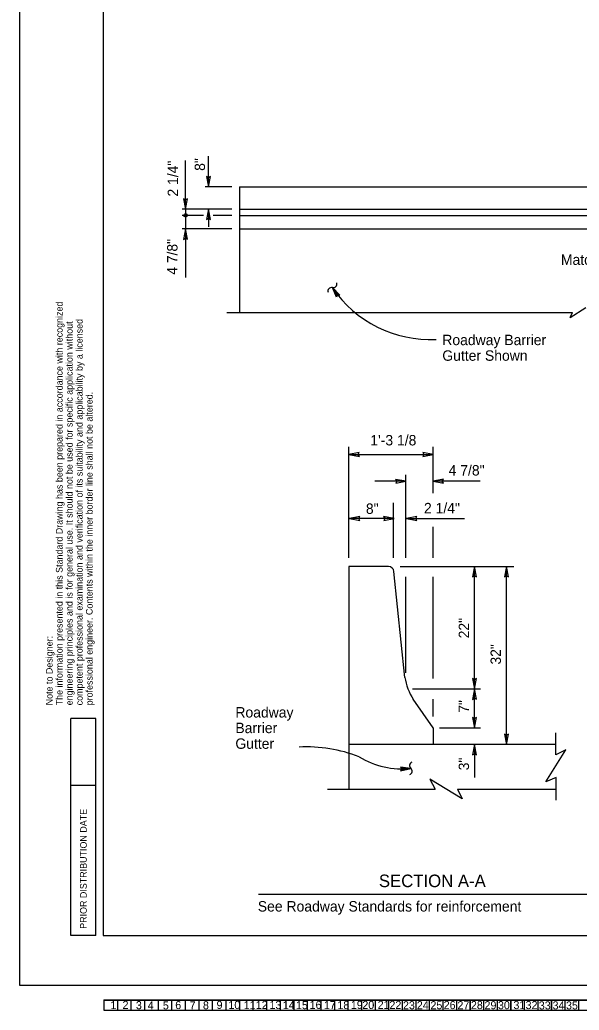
# Model space of a CAD drawing. Extents: x 0 to 2.83, y -0.03 to 1.83.
# Drawn here: x 0 to 0.699, y -0.031 to 1.206 of the extents above; entities that cross this region are included whole.
import ezdxf

# ---------------------------------------------------------------- set-up
doc = ezdxf.new("R2010")
doc.units = 0
for name, color, linetype in [('1', 7, 'Continuous'), ('10', 7, 'Continuous'), ('11', 7, 'Continuous'), ('12', 7, 'Continuous'), ('13', 7, 'Continuous'), ('14', 7, 'Continuous'), ('15', 7, 'Continuous'), ('16', 7, 'Continuous'), ('17', 7, 'Continuous'), ('18', 7, 'Continuous'), ('19', 7, 'Continuous'), ('2', 7, 'Continuous'), ('20', 7, 'Continuous'), ('21', 7, 'Continuous'), ('22', 7, 'Continuous'), ('23', 7, 'Continuous'), ('24', 7, 'Continuous'), ('25', 7, 'Continuous'), ('26', 7, 'Continuous'), ('27', 7, 'Continuous'), ('28', 7, 'Continuous'), ('29', 7, 'Continuous'), ('3', 7, 'Continuous'), ('30', 7, 'Continuous'), ('31', 7, 'Continuous'), ('32', 7, 'Continuous'), ('33', 7, 'Continuous'), ('34', 7, 'Continuous'), ('35', 7, 'Continuous'), ('4', 7, 'Continuous'), ('40', 7, 'Continuous'), ('5', 7, 'Continuous'), ('50', 7, 'Continuous'), ('54', 7, 'Continuous'), ('55', 7, 'Continuous'), ('57', 7, 'Continuous'), ('6', 7, 'Continuous'), ('62', 7, 'Continuous'), ('63', 7, 'Continuous'), ('7', 7, 'Continuous'), ('8', 7, 'Continuous'), ('9', 7, 'Continuous')]:
    doc.layers.add(name, color=color, linetype=linetype)

msp = doc.modelspace()

# ---------------------------------------------------------------- linework, layer by layer
at = {"layer": '40'}
for p, q in [((0.2743, 0.9973), (0.8822, 0.9973)), ((0.2743, 0.9973), (0.2743, 0.8407)), ((0.2743, 0.9696), (0.8822, 0.9696)), ((0.2743, 0.9618), (0.8822, 0.9618)), ((0.2743, 0.9448), (0.8822, 0.9448))]:
    msp.add_line(p, q, dxfattribs=at)
at = {"layer": '50'}
for p, q in [((0.4603, 0.5232), (0.411, 0.5232)), ((0.411, 0.5232), (0.411, 0.301)), ((0.4808, 0.3848), (0.4672, 0.517)), ((0.5161, 0.3218), (0.4912, 0.3576)), ((0.5161, 0.3218), (0.5161, 0.301)), ((0.411, 0.301), (0.411, 0.2454)), ((0.6693, 0.301), (0.411, 0.301))]:
    msp.add_line(p, q, dxfattribs=at)
for centre, radius, start, end in [((0.4603, 0.5162), 0.00694, 5.8395, 90), ((0.5494, 0.3955), 0.0694, 188.8949, 213.1061)]:
    msp.add_arc(centre, radius, start, end, dxfattribs=at)
at = {"layer": '54'}
for points in [[(0.2356, 0.9973), (0.238, 1.0103), (0.2356, 1.0088), (0.2332, 1.0102)], [(0.207, 0.9696), (0.2094, 0.9826), (0.207, 0.981), (0.2046, 0.9824)], [(0.2356, 0.9696), (0.2333, 0.9566), (0.2356, 0.9581), (0.238, 0.9567)], [(0.207, 0.9448), (0.2046, 0.9318), (0.207, 0.9333), (0.2094, 0.932)], [(0.411, 0.6632), (0.424, 0.6608), (0.4225, 0.6632), (0.4239, 0.6656)], [(0.5161, 0.6632), (0.5031, 0.6656), (0.5046, 0.6632), (0.5032, 0.6608)], [(0.4822, 0.6298), (0.4692, 0.6321), (0.4707, 0.6298), (0.4694, 0.6274)], [(0.5161, 0.6298), (0.5291, 0.6274), (0.5276, 0.6298), (0.5289, 0.6322)], [(0.4117, 0.5833), (0.4247, 0.5809), (0.4232, 0.5833), (0.4246, 0.5857)], [(0.4673, 0.5833), (0.4543, 0.5857), (0.4558, 0.5833), (0.4544, 0.5809)], [(0.4829, 0.5833), (0.4959, 0.5809), (0.4944, 0.5833), (0.4957, 0.5857)], [(0.5677, 0.5232), (0.5653, 0.5102), (0.5677, 0.5117), (0.5701, 0.5104)], [(0.6077, 0.5232), (0.6053, 0.5102), (0.6077, 0.5117), (0.6101, 0.5104)], [(0.5677, 0.3704), (0.5701, 0.3834), (0.5677, 0.3819), (0.5653, 0.3833)], [(0.5677, 0.3704), (0.5653, 0.3574), (0.5677, 0.3589), (0.5701, 0.3576)], [(0.5677, 0.3218), (0.5701, 0.3348), (0.5677, 0.3333), (0.5653, 0.3346)], [(0.6077, 0.301), (0.6101, 0.314), (0.6077, 0.3125), (0.6053, 0.3138)], [(0.5677, 0.301), (0.5653, 0.288), (0.5677, 0.2895), (0.5701, 0.2881)]]:
    msp.add_lwpolyline(points, close=True, dxfattribs=at)
at = {"layer": '55'}
for p, q in [((0.207, 0.9696), (0.207, 1.0302)), ((0.2356, 0.9973), (0.2356, 1.0357)), ((0.2647, 0.9973), (0.2315, 0.9973)), ((0.2647, 0.9696), (0.2028, 0.9696)), ((0.207, 0.9696), (0.207, 0.9448)), ((0.2356, 0.9696), (0.2356, 0.9476)), ((0.2294, 0.9618), (0.2028, 0.9618)), ((0.2647, 0.9618), (0.2414, 0.9618)), ((0.2647, 0.9448), (0.2028, 0.9448)), ((0.207, 0.9448), (0.207, 0.8841)), ((0.6871, 0.8343), (0.707, 0.8466)), ((0.2587, 0.8405), (0.6796, 0.8405)), ((0.6743, 0.8404), (0.6902, 0.8404)), ((0.6871, 0.8343), (0.6902, 0.8404)), ((0.411, 0.5343), (0.411, 0.6728)), ((0.5161, 0.6147), (0.5161, 0.6728)), ((0.411, 0.6632), (0.5161, 0.6632)), ((0.4822, 0.5343), (0.4822, 0.6376)), ((0.4822, 0.6298), (0.4434, 0.6298)), ((0.5749, 0.6298), (0.5161, 0.6298)), ((0.4666, 0.5343), (0.4666, 0.6027)), ((0.4673, 0.5833), (0.4117, 0.5833)), ((0.4829, 0.5833), (0.5555, 0.5833)), ((0.5161, 0.5343), (0.5161, 0.573)), ((0.4749, 0.5232), (0.6171, 0.5232)), ((0.5677, 0.3704), (0.5677, 0.5232)), ((0.6077, 0.301), (0.6077, 0.5232)), ((0.4822, 0.3906), (0.4822, 0.5105)), ((0.5161, 0.3834), (0.5161, 0.5105)), ((0.4904, 0.3704), (0.5753, 0.3704)), ((0.5677, 0.3218), (0.5677, 0.3704)), ((0.5161, 0.3358), (0.5161, 0.3575)), ((0.5241, 0.3218), (0.5753, 0.3218)), ((0.6693, 0.288), (0.6693, 0.3156)), ((0.5677, 0.301), (0.5677, 0.2597)), ((0.657, 0.2542), (0.6818, 0.2942)), ((0.6818, 0.2942), (0.6693, 0.288)), ((0.6697, 0.2599), (0.657, 0.2542)), ((0.6697, 0.2315), (0.6697, 0.2599)), ((0.5522, 0.2331), (0.5122, 0.2579)), ((0.5122, 0.2579), (0.5185, 0.2454)), ((0.3842, 0.2454), (0.5185, 0.2454)), ((0.5467, 0.2454), (0.5522, 0.2331)), ((0.5467, 0.2454), (0.6697, 0.2454))]:
    msp.add_line(p, q, dxfattribs=at)
for points in [[(0.3903, 0.8716), (0.3995, 0.8622), (0.3973, 0.8621), (0.392, 0.8691), (0.3965, 0.8615), (0.3956, 0.8595), (0.3903, 0.8716)], [(0.3935, 0.8679), (0.3973, 0.8628), (0.3983, 0.8628), (0.3911, 0.8704), (0.3955, 0.8609), (0.3959, 0.8619), (0.3927, 0.8671)], [(0.4883, 0.2712), (0.4753, 0.2728), (0.4766, 0.271), (0.4853, 0.271), (0.4766, 0.27), (0.4756, 0.2681), (0.4883, 0.2712)], [(0.4835, 0.2715), (0.4771, 0.2714), (0.4765, 0.2723), (0.4869, 0.2711), (0.4767, 0.2688), (0.4772, 0.2698), (0.4833, 0.2703)]]:
    msp.add_lwpolyline(points, dxfattribs=at)
msp.add_circle((0.207, 0.9618), 0.00214, dxfattribs=at)
for centre, radius, start, end in [((0.3894, 0.867), 0.0047, 78.7125, 195.1185), ((0.3913, 0.8762), 0.0047, 258.7125, 15.1185), ((0.5124, 0.954), 0.1473, 214.0105, 272.8594), ((0.3581, 0.1167), 0.1813, 68.7429, 92.9324), ((0.4767, 0.37), 0.0995, 237.9072, 276.7321), ((0.4914, 0.2747), 0.0047, 112.0894, 228.4955), ((0.4852, 0.2677), 0.0047, 292.0894, 48.4955)]:
    msp.add_arc(centre, radius, start, end, dxfattribs=at)
at = {"layer": '57'}
msp.add_line((0.7833, 0.1135), (0.2981, 0.1135), dxfattribs=at)
at = {"layer": '62'}
for p, q in [((0.1049, -0.018), (1.1717, -0.018)), ((0.1049, -0.018), (0.1049, -0.0307)), ((0.105, -0.0181), (1.1718, -0.0181)), ((0.105, -0.0181), (0.105, -0.0308)), ((0.1219, -0.018), (0.1219, -0.0307)), ((0.1219, -0.0181), (0.1219, -0.0308)), ((0.1388, -0.018), (0.1388, -0.0307)), ((0.1388, -0.0181), (0.1388, -0.0308)), ((0.1557, -0.018), (0.1557, -0.0307)), ((0.1558, -0.0181), (0.1558, -0.0308)), ((0.1727, -0.018), (0.1727, -0.0307)), ((0.1727, -0.0181), (0.1727, -0.0308)), ((0.1896, -0.018), (0.1896, -0.0307)), ((0.1896, -0.0181), (0.1896, -0.0308)), ((0.2065, -0.018), (0.2065, -0.0307)), ((0.2066, -0.0181), (0.2066, -0.0308)), ((0.2235, -0.018), (0.2235, -0.0307)), ((0.2235, -0.0181), (0.2235, -0.0308)), ((0.2404, -0.018), (0.2404, -0.0307)), ((0.2404, -0.0181), (0.2404, -0.0308)), ((0.2573, -0.018), (0.2573, -0.0307)), ((0.2574, -0.0181), (0.2574, -0.0308)), ((0.2743, -0.018), (0.2743, -0.0307)), ((0.2743, -0.0181), (0.2743, -0.0308)), ((0.2912, -0.018), (0.2912, -0.0307)), ((0.2912, -0.0181), (0.2912, -0.0308)), ((0.3081, -0.018), (0.3081, -0.0307)), ((0.3082, -0.0181), (0.3082, -0.0308)), ((0.3251, -0.018), (0.3251, -0.0307)), ((0.3251, -0.0181), (0.3251, -0.0308)), ((0.342, -0.018), (0.342, -0.0307)), ((0.342, -0.0181), (0.342, -0.0308)), ((0.3589, -0.018), (0.3589, -0.0307)), ((0.359, -0.0181), (0.359, -0.0308)), ((0.3759, -0.018), (0.3759, -0.0307)), ((0.3759, -0.0181), (0.3759, -0.0308)), ((0.3928, -0.018), (0.3928, -0.0307)), ((0.3928, -0.0181), (0.3928, -0.0308)), ((0.4097, -0.018), (0.4097, -0.0307)), ((0.4098, -0.0181), (0.4098, -0.0308)), ((0.4267, -0.018), (0.4267, -0.0307)), ((0.4267, -0.0181), (0.4267, -0.0308)), ((0.4436, -0.018), (0.4436, -0.0307)), ((0.4436, -0.0181), (0.4436, -0.0308)), ((0.4605, -0.018), (0.4605, -0.0307)), ((0.4606, -0.0181), (0.4606, -0.0308)), ((0.4775, -0.018), (0.4775, -0.0307)), ((0.4775, -0.0181), (0.4775, -0.0308)), ((0.4944, -0.018), (0.4944, -0.0307)), ((0.4944, -0.0181), (0.4944, -0.0308)), ((0.5113, -0.018), (0.5113, -0.0307)), ((0.5114, -0.0181), (0.5114, -0.0308)), ((0.5283, -0.018), (0.5283, -0.0307)), ((0.5283, -0.0181), (0.5283, -0.0308)), ((0.5452, -0.018), (0.5452, -0.0307)), ((0.5452, -0.0181), (0.5452, -0.0308)), ((0.5621, -0.018), (0.5621, -0.0307)), ((0.5622, -0.0181), (0.5622, -0.0308)), ((0.5791, -0.018), (0.5791, -0.0307)), ((0.5791, -0.0181), (0.5791, -0.0308)), ((0.596, -0.018), (0.596, -0.0307)), ((0.596, -0.0181), (0.596, -0.0308)), ((0.6129, -0.018), (0.6129, -0.0307)), ((0.613, -0.0181), (0.613, -0.0308)), ((0.6299, -0.018), (0.6299, -0.0307)), ((0.6299, -0.0181), (0.6299, -0.0308)), ((0.6468, -0.018), (0.6468, -0.0307)), ((0.6468, -0.0181), (0.6468, -0.0308)), ((0.6637, -0.018), (0.6637, -0.0307)), ((0.6638, -0.0181), (0.6638, -0.0308)), ((0.6807, -0.018), (0.6807, -0.0307)), ((0.6807, -0.0181), (0.6807, -0.0308)), ((0.6976, -0.018), (0.6976, -0.0307)), ((0.6976, -0.0181), (0.6976, -0.0308)), ((0.1049, -0.0307), (1.1717, -0.0307)), ((0.105, -0.0308), (1.1718, -0.0308))]:
    msp.add_line(p, q, dxfattribs=at)
at = {"layer": '63'}
for p, q in [((0, 0), (0, 1.8333)), ((0.0638, 0.0624), (0.0638, 0.3333)), ((0.0951, 0.3333), (0.0638, 0.3333)), ((0.0951, 0.0624), (0.0951, 0.3333)), ((0.0951, 0.2499), (0.0638, 0.2499)), ((0.0951, 0.0624), (0.0638, 0.0624)), ((2.8333, 0), (0, 0))]:
    msp.add_line(p, q, dxfattribs=at)
msp.add_lwpolyline([(2.7292, 1.7708), (0.1042, 1.7708), (0.1042, 0.0624), (2.7292, 0.0624)], close=True, dxfattribs=at)

# ---------------------------------------------------------------- texts
at = {"layer": '1'}
for p in [(0.1132, -0.0294), (0.1132, -0.0295)]:
    msp.add_text('1', height=0.01, rotation=360, dxfattribs=at).set_placement(p)
at = {"layer": '10'}
msp.add_text('10', height=0.01, rotation=360, dxfattribs=at).set_placement((0.2605, -0.0293))
msp.add_text('10', height=0.01, rotation=360, dxfattribs=at).set_placement((0.2605, -0.0293))
at = {"layer": '11'}
msp.add_text('11', height=0.01, rotation=360, dxfattribs=at).set_placement((0.2796, -0.0294))
msp.add_text('11', height=0.01, rotation=360, dxfattribs=at).set_placement((0.2796, -0.0294))
at = {"layer": '12'}
msp.add_text('12', height=0.01, rotation=360, dxfattribs=at).set_placement((0.2947, -0.0293))
msp.add_text('12', height=0.01, rotation=360, dxfattribs=at).set_placement((0.2947, -0.0293))
at = {"layer": '13'}
msp.add_text('13', height=0.01, rotation=360, dxfattribs=at).set_placement((0.3118, -0.0293))
msp.add_text('13', height=0.01, rotation=360, dxfattribs=at).set_placement((0.3118, -0.0293))
at = {"layer": '14'}
for p in [(0.3284, -0.0294), (0.3285, -0.0294)]:
    msp.add_text('14', height=0.01, rotation=360, dxfattribs=at).set_placement(p)
at = {"layer": '15'}
msp.add_text('15', height=0.01, rotation=360, dxfattribs=at).set_placement((0.3449, -0.0295))
msp.add_text('15', height=0.01, rotation=360, dxfattribs=at).set_placement((0.3449, -0.0295))
at = {"layer": '16'}
msp.add_text('16', height=0.01, rotation=360, dxfattribs=at).set_placement((0.3619, -0.0292))
msp.add_text('16', height=0.01, rotation=360, dxfattribs=at).set_placement((0.3619, -0.0292))
at = {"layer": '17'}
msp.add_text('17', height=0.01, rotation=360, dxfattribs=at).set_placement((0.3797, -0.0295))
msp.add_text('17', height=0.01, rotation=360, dxfattribs=at).set_placement((0.3797, -0.0295))
at = {"layer": '18'}
msp.add_text('18', height=0.01, rotation=360, dxfattribs=at).set_placement((0.3966, -0.0294))
msp.add_text('18', height=0.01, rotation=360, dxfattribs=at).set_placement((0.3966, -0.0294))
at = {"layer": '19'}
msp.add_text('19', height=0.01, rotation=360, dxfattribs=at).set_placement((0.4134, -0.0292))
msp.add_text('19', height=0.01, rotation=360, dxfattribs=at).set_placement((0.4134, -0.0292))
at = {"layer": '2'}
msp.add_text('2', height=0.01, rotation=360, dxfattribs=at).set_placement((0.1283, -0.0293))
msp.add_text('2', height=0.01, rotation=360, dxfattribs=at).set_placement((0.1283, -0.0293))
at = {"layer": '20'}
for p in [(0.4277, -0.0293), (0.4278, -0.0293)]:
    msp.add_text('20', height=0.01, rotation=360, dxfattribs=at).set_placement(p)
at = {"layer": '21'}
msp.add_text('21', height=0.01, rotation=360, dxfattribs=at).set_placement((0.4469, -0.0291))
msp.add_text('21', height=0.01, rotation=360, dxfattribs=at).set_placement((0.4469, -0.0291))
at = {"layer": '22'}
msp.add_text('22', height=0.01, rotation=360, dxfattribs=at).set_placement((0.4616, -0.0293))
msp.add_text('22', height=0.01, rotation=360, dxfattribs=at).set_placement((0.4616, -0.0293))
at = {"layer": '23'}
msp.add_text('23', height=0.01, rotation=360, dxfattribs=at).set_placement((0.4785, -0.0296))
msp.add_text('23', height=0.01, rotation=360, dxfattribs=at).set_placement((0.4785, -0.0296))
at = {"layer": '24'}
msp.add_text('24', height=0.01, rotation=360, dxfattribs=at).set_placement((0.4958, -0.0296))
msp.add_text('24', height=0.01, rotation=360, dxfattribs=at).set_placement((0.4958, -0.0296))
at = {"layer": '25'}
msp.add_text('25', height=0.01, rotation=360, dxfattribs=at).set_placement((0.5128, -0.0296))
msp.add_text('25', height=0.01, rotation=360, dxfattribs=at).set_placement((0.5128, -0.0296))
at = {"layer": '26'}
msp.add_text('26', height=0.01, rotation=360, dxfattribs=at).set_placement((0.5293, -0.0294))
msp.add_text('26', height=0.01, rotation=360, dxfattribs=at).set_placement((0.5293, -0.0294))
at = {"layer": '27'}
msp.add_text('27', height=0.01, rotation=360, dxfattribs=at).set_placement((0.5465, -0.0296))
msp.add_text('27', height=0.01, rotation=360, dxfattribs=at).set_placement((0.5465, -0.0296))
at = {"layer": '28'}
msp.add_text('28', height=0.01, rotation=360, dxfattribs=at).set_placement((0.5633, -0.0294))
msp.add_text('28', height=0.01, rotation=360, dxfattribs=at).set_placement((0.5633, -0.0294))
at = {"layer": '29'}
msp.add_text('29', height=0.01, rotation=360, dxfattribs=at).set_placement((0.5803, -0.0296))
msp.add_text('29', height=0.01, rotation=360, dxfattribs=at).set_placement((0.5803, -0.0296))
at = {"layer": '3'}
for p in [(0.145, -0.0295), (0.145, -0.0296)]:
    msp.add_text('3', height=0.01, rotation=360, dxfattribs=at).set_placement(p)
at = {"layer": '30'}
msp.add_text('30', height=0.01, rotation=360, dxfattribs=at).set_placement((0.5971, -0.0295))
msp.add_text('30', height=0.01, rotation=360, dxfattribs=at).set_placement((0.5971, -0.0295))
at = {"layer": '31'}
msp.add_text('31', height=0.01, rotation=360, dxfattribs=at).set_placement((0.6164, -0.0294))
msp.add_text('31', height=0.01, rotation=360, dxfattribs=at).set_placement((0.6164, -0.0294))
at = {"layer": '32'}
msp.add_text('32', height=0.01, rotation=360, dxfattribs=at).set_placement((0.6316, -0.0294))
msp.add_text('32', height=0.01, rotation=360, dxfattribs=at).set_placement((0.6316, -0.0294))
at = {"layer": '33'}
msp.add_text('33', height=0.01, rotation=360, dxfattribs=at).set_placement((0.6481, -0.0298))
msp.add_text('33', height=0.01, rotation=360, dxfattribs=at).set_placement((0.6481, -0.0298))
at = {"layer": '34'}
msp.add_text('34', height=0.01, rotation=360, dxfattribs=at).set_placement((0.6653, -0.0298))
msp.add_text('34', height=0.01, rotation=360, dxfattribs=at).set_placement((0.6653, -0.0298))
at = {"layer": '35'}
msp.add_text('35', height=0.01, rotation=360, dxfattribs=at).set_placement((0.6821, -0.0298))
msp.add_text('35', height=0.01, rotation=360, dxfattribs=at).set_placement((0.6821, -0.0298))
at = {"layer": '4'}
for p in [(0.1597, -0.0298), (0.1597, -0.0299)]:
    msp.add_text('4', height=0.01, rotation=360, dxfattribs=at).set_placement(p)
at = {"layer": '5'}
msp.add_text('5', height=0.01, rotation=360, dxfattribs=at).set_placement((0.1786, -0.0298))
msp.add_text('5', height=0.01, rotation=360, dxfattribs=at).set_placement((0.1786, -0.0298))
at = {"layer": '57'}
for s, p in [('2 1/4"', (0.1976, 0.9853)), ('8"', (0.2313, 1.0174)), ('4 7/8"', (0.1969, 0.8876)), ('22"', (0.561, 0.4336)), ('32"', (0.6008, 0.4008)), ('7"', (0.561, 0.3406)), ('3"', (0.561, 0.2688))]:
    msp.add_text(s, height=0.01297, rotation=90, dxfattribs=at).set_placement(p)
for s, height, p in [('Match Toe', 0.01302, (0.6757, 0.8999)), ('Roadway Barrier', 0.013025, (0.5276, 0.7997)), ('Gutter Shown', 0.013025, (0.5276, 0.7802)), ("1'-3 1/8", 0.01302, (0.4377, 0.6745)), ('4 7/8" ', 0.01302, (0.5355, 0.6369)), ('8"', 0.01302, (0.4322, 0.589)), ('2 1/4"', 0.01302, (0.5047, 0.5897)), ('Roadway', 0.01302, (0.2692, 0.3347)), ('Barrier', 0.01302, (0.2692, 0.3152)), ('Gutter', 0.01302, (0.2692, 0.2956)), ('SECTION A-A', 0.015625, (0.4484, 0.1229)), ('See Roadway Standards for reinforcement', 0.013021, (0.2972, 0.0924))]:
    msp.add_text(s, height=height, dxfattribs=at).set_placement(p)
at = {"layer": '6'}
msp.add_text('6', height=0.01, rotation=360, dxfattribs=at).set_placement((0.1941, -0.0294))
msp.add_text('6', height=0.01, rotation=360, dxfattribs=at).set_placement((0.1941, -0.0294))
at = {"layer": '62'}
for s, height, p in [('The information presented in this Standard Drawing has been prepared in accordance with recognized', 0.008333, (0.0534, 0.3499)), ('engineering principles and is for general use. It should not be used for specific application without', 0.0083333, (0.0659, 0.3499)), ('competent professional examination and verification of its suitability and applicability by a licensed', 0.0083333, (0.0784, 0.3499)), ('professional engineer. Contents within the inner border line shall not be altered.', 0.008333, (0.0909, 0.3499)), ('Note to Designer:', 0.008333, (0.0409, 0.3499))]:
    msp.add_text(s, height=height, rotation=90, dxfattribs=at).set_placement(p)
at = {"layer": '63'}
msp.add_text('PRIOR DISTRIBUTION DATE', height=0.008333, rotation=90, dxfattribs=at).set_placement((0.0836, 0.0708))
at = {"layer": '7'}
for p in [(0.2121, -0.0296), (0.2121, -0.0297)]:
    msp.add_text('7', height=0.01, rotation=360, dxfattribs=at).set_placement(p)
at = {"layer": '8'}
msp.add_text('8', height=0.01, rotation=360, dxfattribs=at).set_placement((0.2287, -0.0296))
msp.add_text('8', height=0.01, rotation=360, dxfattribs=at).set_placement((0.2287, -0.0296))
at = {"layer": '9'}
for p in [(0.2457, -0.0292), (0.2457, -0.0293)]:
    msp.add_text('9', height=0.01, rotation=360, dxfattribs=at).set_placement(p)

doc.saveas('drawing.dxf')
